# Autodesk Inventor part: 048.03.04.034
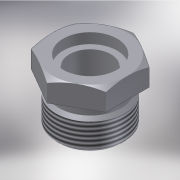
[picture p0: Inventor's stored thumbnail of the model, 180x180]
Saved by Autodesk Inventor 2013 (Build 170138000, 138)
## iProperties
Shininess: 20.0
Angle Display Precision: 2
Document Length Units: 11269
Document Angle Units: 11279
Document Time Units: 11290
Document Mass Units: 11283
Document Length Units Precision: 3
Document Angle Units Precision: 2
Created: 2002-08
Part Number: 048.03.04.034
Material: Steel, Mild
Document SubType Name: Modeling
Designer: SOleg
Mass: 121.294 g
Surface Area: 67.9132 cm^2
Volume: 15.4318 cm^3
Density: 7.86 g/cm^3
Density: 0.0
Volumn: 0.0
Area: 0.0
PropertySet Name: Model Information
Control State: 0
Master: False
Checked Out: True
Checked Out Date: 2008-10-15
Last Check In Date: 2008-10-15
Author: SOleg
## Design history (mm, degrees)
node "WorkPlane1"
node "WorkPlane2"
node "WorkPlane7"
revolve "Вращение3" stored, may be unused: angle "d84" = 90 deg
feature "Резьба2" dims "d85" = 10, "d86" = 0
sketch "Эскиз9"
  geometry: L1 (0, -20.785)-(-18, -10.392); L2 (-18, -10.392)-(-18, 10.392); L3 (-18, 10.392)-(0, 20.785); L4 (0, 20.785)-(18, 10.392); L5 (18, 10.392)-(18, -10.392); L6 (18, -10.392)-(0, -20.785); C1 r 18 at (0, 0) reference; 1 further point
  constraints: 12 end point, 1 coincident, 11 other
  dimensions: "d87" = 36 distance between parallel lines of L3 L6
extrude "Выдавливание4" sketch "Эскиз9" stored distance "d88" = 10; taper "d89" = 0 deg
body "Solid1"
sketch "Эскиз8"
  geometry: L1 (0.578, -6.289)-(-17.422, -6.289); L2 (-17.422, -6.289)-(-24.422, -10.33); L3 (-24.422, -10.33)-(-24.422, -16.289); L4 (-24.422, -16.289)-(-14.422, -16.289); L5 (-14.422, -16.289)-(-14.422, -21.289); L6 (-14.422, -21.289)-(-15.922, -22.789); L7 (-15.922, -22.789)-(-15.922, -34.289); L8 (-15.922, -34.289)-(-13.922, -36.289); L9 (-13.922, -36.289)-(0.578, -36.289); L10 (0.578, -36.289)-(0.578, -6.289); L11 (-12.922, -36.289)-(-9.422, -25.828); L12 (-9.422, -25.828)-(-9.422, -11.289); L13 (-9.422, -11.289)-(-12.422, -11.289); L14 (-12.422, -11.289)-(-12.422, -6.289)
  constraints: 28 end point, 6 parallel, 4 perpendicular, 2 point on line, 1 horizontal, 1 other
  dimensions: "d69" = 5 distance of L4.end L5.end; "d70" = 45 deg angle of L7 L6; "d71" = 2 horizontal distance of L7.end L8.end; "d72" = 30 diameter of L5 L10; "d73" = 33 diameter of L7 L10; "d74" = 27 diameter of L11.start L10; "d75" = 20 diameter of L12 L10; "d76" = 18.5 deg angle of L11 L12; "d77" = 26 diameter of L14 L10; "d78" = 5 distance of L13.end L14.end; "d79" = 20 distance between parallel lines of L4 L9; "d80" = 30 distance between parallel lines of L1 L9; "d81" = 30 deg angle of L2 L1; "d82" = 36 diameter of L1.end L10; "d83" = 50 diameter of L3 L10
other parameters: "d0" = 0, "d3" = 0 (derived), "d6" = 135 deg (derived), "d8" = 15.7 (derived), "d10" = 16.5 (derived), "d12" = 5 (derived), "d14" = 0.5 (derived), "d16" = 135 deg (derived), "d18" = 15 (derived), "d24" = 60 deg (derived), "d26" = 36 (derived), "d28" = 36 (derived), "d30" = 20.78461 (derived), "d32" = 20.78461 (derived), "d34" = 120 deg (derived), "d36" = 120 deg (derived), "d42" = 1 (derived), "d44" = 0 (derived), "d45" = 45 deg (derived), "d48" = 26 (derived), "d52" = 19 (derived)
